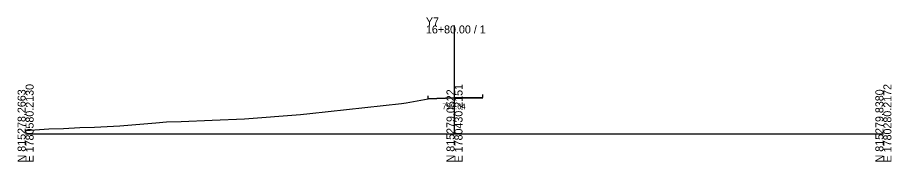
# Model space of a CAD drawing. Extents: x -26 to 2903, y -10 to 5536.
# Drawn here: x 1297.2 to 1602.8, y 2490.3 to 2540.8 of the extents above; entities that cross this region are included whole.
import ezdxf

# ---------------------------------------------------------------- set-up
doc = ezdxf.new("R2010")
doc.units = 0
for name, color, linetype in [('Exist Cross Section Cell', 7, 'Continuous'), ('Exist XS Center Line Elevation Label', 7, 'Continuous'), ('Exist XS Ground Line', 7, 'Continuous'), ('Prop XS EOT Tick Mark', 7, 'Continuous'), ('Prop XS Finish Grade Pavement', 7, 'Continuous')]:
    doc.layers.add(name, color=color, linetype=linetype)

msp = doc.modelspace()

# ---------------------------------------------------------------- linework, layer by layer
at = {"layer": 'Exist Cross Section Cell'}
for p, q in [((1450, 2500), (1450, 2538)), ((1300, 2500), (1450, 2500)), ((1450, 2500), (1600, 2500))]:
    msp.add_line(p, q, dxfattribs=at)
at = {"layer": 'Exist XS Ground Line'}
for p, q in [((1399.39, 2507.15), (1431.48, 2510.63)), ((1431.48, 2510.63), (1433.07, 2510.91)), ((1433.07, 2510.91), (1440.8, 2512.26)), ((1440.8, 2512.26), (1446.82, 2512.51)), ((1446.82, 2512.51), (1449.82, 2512.64)), ((1449.82, 2512.64), (1452.32, 2512.63)), ((1452.32, 2512.63), (1459.96, 2512.67)), ((1376.51, 2505.24), (1396.15, 2506.79)), ((1396.15, 2506.79), (1399.39, 2507.15)), ((1332.95, 2502.86), (1345.57, 2503.92)), ((1345.57, 2503.92), (1349.29, 2504.23)), ((1349.29, 2504.23), (1354.35, 2504.36)), ((1354.35, 2504.36), (1365.26, 2504.78)), ((1365.26, 2504.78), (1376.51, 2505.24)), ((1300, 2501.27), (1301.58, 2501.34)), ((1301.58, 2501.34), (1308.08, 2501.75)), ((1308.08, 2501.75), (1313.29, 2501.94)), ((1313.29, 2501.94), (1318.91, 2502.21)), ((1318.91, 2502.21), (1324.1, 2502.39)), ((1324.1, 2502.39), (1332.95, 2502.86))]:
    msp.add_line(p, q, dxfattribs=at)
at = {"layer": 'Prop XS EOT Tick Mark'}
for p, q in [((1440.8, 2512.39), (1440.8, 2513.39)), ((1459.96, 2512.79), (1459.96, 2513.79))]:
    msp.add_line(p, q, dxfattribs=at)
at = {"layer": 'Prop XS Finish Grade Pavement'}
for p, q in [((1446.81, 2512.64), (1449.82, 2512.76)), ((1449.82, 2512.76), (1452.32, 2512.76)), ((1452.32, 2512.76), (1459.96, 2512.79)), ((1440.8, 2512.39), (1446.81, 2512.64))]:
    msp.add_line(p, q, dxfattribs=at)

# ---------------------------------------------------------------- texts
at = {"layer": 'Exist Cross Section Cell'}
for s, p in [('Y7', (1440, 2538)), ('16+80.00 / 1', (1440, 2535.2))]:
    msp.add_text(s, height=2.8, dxfattribs=at).set_placement(p)
for s, p in [('E 1780580.2130', (1302.8, 2490)), ('E 1780430.2151', (1452.8, 2490)), ('E 1780280.2172', (1602.8, 2490)), ('N 815278.2663', (1300, 2490)), ('N 815279.0522', (1450, 2490)), ('N 815279.8380', (1600, 2490))]:
    msp.add_text(s, height=2.8, rotation=90, dxfattribs=at).set_placement(p)
at = {"layer": 'Exist XS Center Line Elevation Label'}
msp.add_text('799.64', height=2, dxfattribs=at).set_placement((1445.72, 2508.64))

doc.saveas('drawing.dxf')
